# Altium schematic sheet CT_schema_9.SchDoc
size 147 x 119 mm
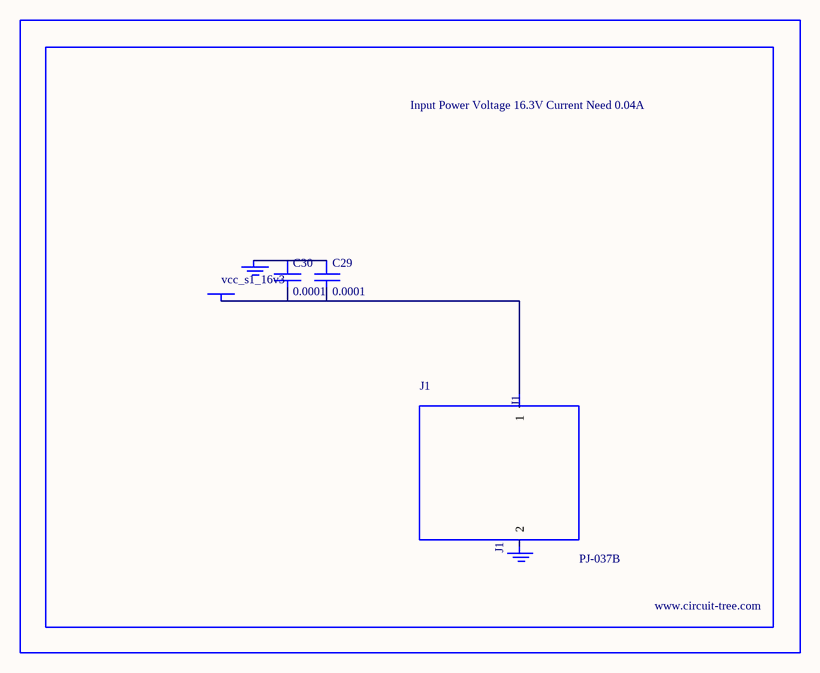
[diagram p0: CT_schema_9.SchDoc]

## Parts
BORDER8  (no value)
C29  0.0001  [EXV-9H]
C30  0.0001  [EXV-9H]
GND_INSTANCE_8_0  (no value)
GND_INSTANCE_8_1  (no value)
J1  PJ-037B  [PJ-037B_PACKAGE]
POWER_INSTANCE_8_0  vcc_s1_16v3

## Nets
NetC29_1: C29.1 C30.1 GND_INSTANCE_8_0.0(GND)
NetC29_2: C29.2 C30.2 J1.1 POWER_INSTANCE_8_0.0(PWR)

Not connected (* = marked no-connect by the designer): GND_INSTANCE_8_1 0(GND); J1 2

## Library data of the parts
BORDER8 = BORDER_PAGE8
C29 C30 = EDK107M035A9HAA
GND_INSTANCE_8_0 GND_INSTANCE_8_1 = GND
POWER_INSTANCE_8_0 = PWR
